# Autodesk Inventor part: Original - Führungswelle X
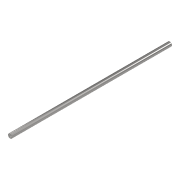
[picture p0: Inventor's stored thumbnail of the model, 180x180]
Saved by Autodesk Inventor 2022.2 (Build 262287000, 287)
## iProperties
Created: 2024-09
Part Number: Original - Führungswelle X
Material: Acciaio inossidabile
Document SubType Name: Modeling
Designer: 18907419
Density: 8 g/cm^3
Appearance: Semilucidato
Author: 18907419
Revision Number: ANY
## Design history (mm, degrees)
feature "Fase1"
node "Solido1"
